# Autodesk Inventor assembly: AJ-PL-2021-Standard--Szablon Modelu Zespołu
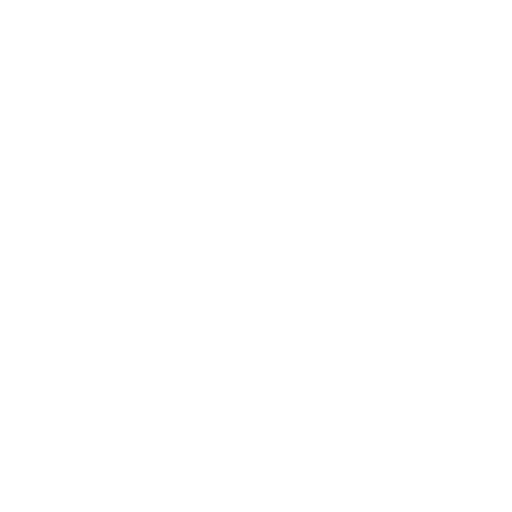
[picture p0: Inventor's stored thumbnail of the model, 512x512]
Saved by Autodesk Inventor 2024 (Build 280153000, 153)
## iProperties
Company: ATC
Shininess: 64.0
Length Units: 11269
Angle Units: 11279
Time Units: 11290
Mass Units: 11283
Length Display Precision: 3
Angle Display Precision: 2
Compacted: True
Created: 2023-03
Part Number: AJ-PL-2021-Standard--Szablon Modelu Zespołu
Document SubType Name: Assembly
Checked By: A.J.
Engr Approved By: Andrzej Jaskulski
Mfg Approved By: Andrzej Jaskulski
Designer: Andrzej Jaskulski
Authority: A.J.
Density: 0.0
Volumn: 0.0
Area: 0.0
PropertySet Name: Model Information
Control State: 0
Master: False
Checked Out: False
Title: A.J.: Kurs R2024-MEP
Author: Andrzej Jaskulski
Revision Number: 1/24
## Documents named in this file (1)
- C:\Users\AndJas\Documents\R2024-MEP\Obszar roboczy\AJ-PL-2024-Standard--Szablon Modelu Zespołu.iam
